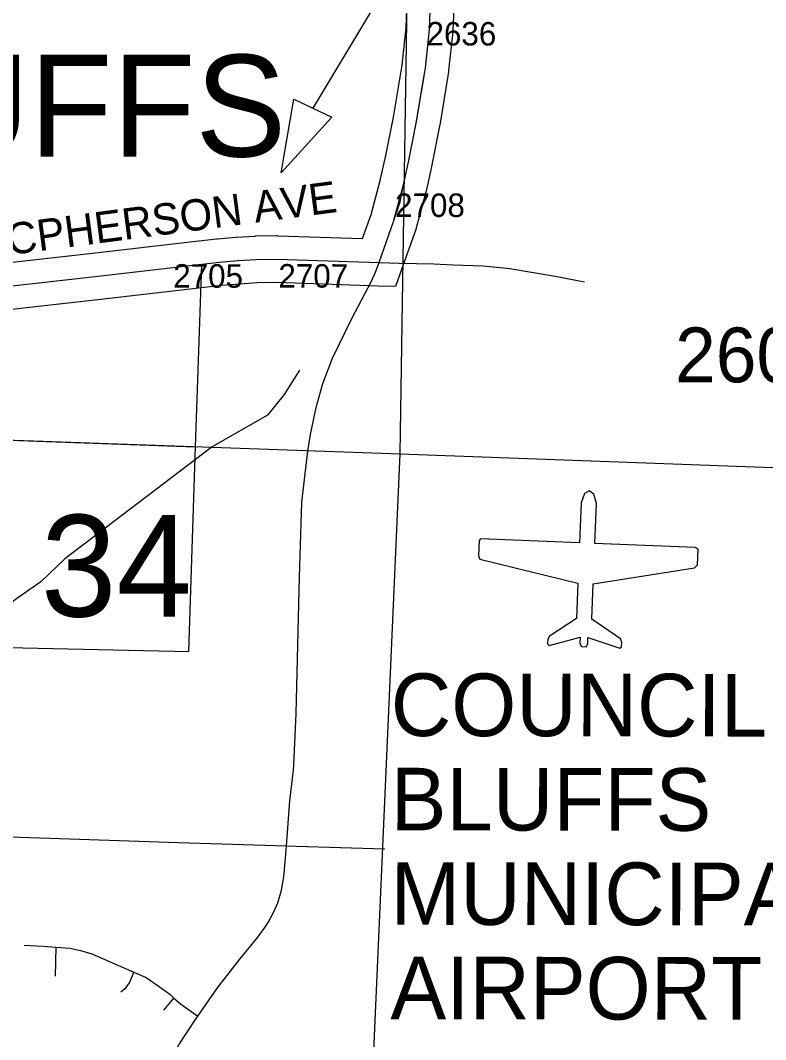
# Model space of a CAD drawing. Extents: x -132.8 to -73.3, y -60 to -26.
# Drawn here: x -118.384 to -117.43, y -50.173 to -48.87 of the extents above; entities that cross this region are included whole.
import ezdxf

# ---------------------------------------------------------------- set-up
doc = ezdxf.new("R2010")
doc.units = 0
for name, color, linetype in [('tdCoAirport', 7, 'Continuous'), ('tdCoAirportTxt', 7, 'Continuous'), ('tdCoCityStreetMajor', 7, 'Continuous'), ('tdCoCityStreetMinor', 7, 'Continuous'), ('tdCoCorpBndry', 7, 'Continuous'), ('tdCoCorpTxt', 7, 'Continuous'), ('tdCoDirctArrow', 7, 'Continuous'), ('tdCoHydroRiver', 7, 'Continuous'), ('tdCoSecRdNmbr', 7, 'Continuous'), ('tdCoSecRdTxt', 7, 'Continuous'), ('tdCoSecRteBand', 7, 'Continuous'), ('tdCoSecRteCL', 7, 'Continuous'), ('tdCoSectLine', 7, 'Continuous'), ('tdCoSectLinePart', 7, 'Continuous'), ('tdCoSectNmbr', 7, 'Continuous'), ('tdCoSurfAsphalt', 7, 'Continuous'), ('tdCoSurfConc', 7, 'Continuous')]:
    doc.layers.add(name, color=color, linetype=linetype)

msp = doc.modelspace()

# ---------------------------------------------------------------- linework, layer by layer
at = {"layer": 'tdCoAirport'}
msp.add_lwpolyline([(-117.6559, -49.4714), (-117.662, -49.4751), (-117.6664, -49.4868), (-117.6685, -49.5381), (-117.7949, -49.533), (-117.7969, -49.5349), (-117.7977, -49.5546), (-117.7959, -49.5587), (-117.6706, -49.5895), (-117.6724, -49.6349), (-117.7069, -49.6572), (-117.7091, -49.6611), (-117.7093, -49.667), (-117.7074, -49.6691), (-117.6674, -49.6588), (-117.6678, -49.6667), (-117.6659, -49.6707), (-117.66, -49.671), (-117.6579, -49.6671), (-117.6576, -49.6592), (-117.6166, -49.6728), (-117.6145, -49.6709), (-117.6143, -49.6649), (-117.6161, -49.6609), (-117.6527, -49.6357), (-117.6508, -49.5903), (-117.5214, -49.5698), (-117.5173, -49.566), (-117.5165, -49.5463), (-117.5204, -49.5441), (-117.6487, -49.5389), (-117.6467, -49.4876), (-117.6484, -49.4816), (-117.6501, -49.4756)], close=True, dxfattribs=at)
at = {"layer": 'tdCoCityStreetMajor'}
msp.add_lwpolyline([(-118.4228, -49.9132), (-118.41, -49.9134), (-118.1814, -49.9211), (-118.0432, -49.9253), (-118.039, -49.8676), (-118.0342, -49.8288), (-118.0337, -49.8224), (-118.0309, -49.7562), (-118.0267, -49.5816), (-118.0234, -49.4859), (-118.0159, -49.421), (-118.0124, -49.3997), (-118.0053, -49.3652), (-117.9967, -49.3343), (-117.9845, -49.302), (-117.9593, -49.2502), (-117.9349, -49.2042), (-117.9292, -49.192), (-117.9248, -49.1798)], dxfattribs=at)
at = {"layer": 'tdCoCityStreetMinor'}
for p, q in [((-118.3385, -50.0918), (-118.3378, -50.0547)), ((-118.2003, -50.1354), (-118.1872, -50.12))]:
    msp.add_line(p, q, dxfattribs=at)
for points in [[(-117.9248, -49.1798), (-117.899, -49.1804), (-117.8546, -49.1815), (-117.8302, -49.1825), (-117.7915, -49.184), (-117.7577, -49.1872), (-117.6995, -49.1973), (-117.6618, -49.2046)], [(-118.1567, -50.143), (-118.1315, -50.1067), (-118.1027, -50.0702), (-118.08, -50.0421), (-118.0719, -50.031), (-118.0667, -50.0231), (-118.0598, -50.0105), (-118.0541, -49.9982), (-118.0497, -49.9819), (-118.0467, -49.9649), (-118.0447, -49.9457), (-118.0432, -49.9253), (-118.0308, -49.9257), (-117.9175, -49.9292)], [(-118.3786, -50.0524), (-118.3543, -50.0536), (-118.3378, -50.0547)], [(-118.3378, -50.0547), (-118.3202, -50.0561), (-118.3068, -50.0589), (-118.2922, -50.0635), (-118.2384, -50.0869)], [(-118.255, -50.112), (-118.2481, -50.1066), (-118.2439, -50.1004), (-118.2384, -50.0869)], [(-118.2384, -50.0869), (-118.2228, -50.0935), (-118.2072, -50.1042), (-118.1926, -50.1151), (-118.1872, -50.12)], [(-118.1872, -50.12), (-118.1789, -50.1273), (-118.1567, -50.143)], [(-118.2083, -50.229), (-118.2006, -50.2142), (-118.1799, -50.1785), (-118.1589, -50.1461), (-118.1567, -50.143)]]:
    msp.add_lwpolyline(points, dxfattribs=at)
at = {"layer": 'tdCoCorpBndry'}
msp.add_lwpolyline([(-118.4192, -49.6715), (-118.168, -49.6767), (-118.1596, -49.4151), (-118.1516, -49.1819), (-118.1293, -49.1793), (-118.1052, -49.1773), (-118.082, -49.1758), (-118.0553, -49.1753), (-117.9248, -49.1798), (-117.9062, -49.1274), (-117.898, -49.102), (-117.894, -49.0821), (-117.8868, -49.0491), (-117.8768, -48.9995), (-117.8684, -48.9481), (-117.8656, -48.9313), (-117.8604, -48.8817), (-117.8589, -48.845)], dxfattribs=at)
at = {"layer": 'tdCoDirctArrow'}
msp.add_lwpolyline([(-117.1819, -48.8561), (-117.933, -48.8556), (-118.0095, -48.9824)], dxfattribs=at)
msp.add_lwpolyline([(-117.9851, -48.9939), (-118.0499, -49.0652), (-118.0338, -48.9709)], close=True, dxfattribs=at)
at = {"layer": 'tdCoHydroRiver'}
msp.add_lwpolyline([(-118.0266, -49.3174), (-118.0464, -49.3484), (-118.0676, -49.3747), (-118.1382, -49.4153), (-118.3267, -49.5586), (-118.3575, -49.5877), (-118.3897, -49.6105), (-118.4219, -49.6365), (-118.4749, -49.6697), (-118.5026, -49.7021), (-118.5162, -49.738), (-118.5248, -49.763), (-118.5361, -49.7738), (-118.5511, -49.8018), (-118.5819, -49.8341), (-118.6048, -49.865), (-118.6578, -49.9551), (-118.7293, -50.092), (-118.7676, -50.1571)], dxfattribs=at)
at = {"layer": 'tdCoSecRteBand'}
for points in [[(-118.4091, -49.1808), (-118.2913, -49.1677), (-118.1552, -49.1521), (-118.1552, -49.1521), (-118.1552, -49.1521), (-118.1551, -49.1521), (-118.1328, -49.1495), (-118.1323, -49.1494), (-118.1318, -49.1494), (-118.1076, -49.1474), (-118.1073, -49.1474), (-118.1071, -49.1474), (-118.0839, -49.1459), (-118.0832, -49.1459), (-118.0825, -49.1458), (-118.0559, -49.1453), (-118.0551, -49.1453), (-118.0543, -49.1454), (-117.9458, -49.1491), (-117.9349, -49.1184), (-117.9232, -49.075), (-117.9162, -49.0429), (-117.9063, -48.9941), (-117.8953, -48.9273), (-117.8903, -48.8795), (-117.8889, -48.844)], [(-117.8289, -48.8462), (-117.8304, -48.8829), (-117.8305, -48.8839), (-117.8306, -48.8848), (-117.8358, -48.9344), (-117.8359, -48.9353), (-117.836, -48.9361), (-117.8472, -49.0043), (-117.8473, -49.0049), (-117.8474, -49.0054), (-117.8574, -49.055), (-117.8575, -49.0552), (-117.8575, -49.0554), (-117.8647, -49.0885), (-117.8649, -49.0892), (-117.865, -49.0899), (-117.8772, -49.1352), (-117.8775, -49.1363), (-117.8779, -49.1374), (-117.8966, -49.1899), (-117.9039, -49.2105), (-117.9259, -49.2098), (-118.0556, -49.2054), (-118.0807, -49.2058), (-118.103, -49.2072), (-118.1264, -49.2091), (-118.1482, -49.2117), (-118.1482, -49.2117), (-118.1482, -49.2117), (-118.1483, -49.2117), (-118.2845, -49.2273), (-118.2845, -49.2273), (-118.2846, -49.2274), (-118.4024, -49.2404)]]:
    msp.add_lwpolyline(points, dxfattribs=at)
at = {"layer": 'tdCoSecRteCL'}
msp.add_lwpolyline([(-118.4058, -49.2106), (-118.2879, -49.1975), (-118.1517, -49.1819), (-118.1516, -49.1819), (-118.1293, -49.1793), (-118.1052, -49.1773), (-118.082, -49.1758), (-118.0553, -49.1753), (-117.9248, -49.1798), (-117.9062, -49.1274), (-117.894, -49.0821), (-117.8868, -49.0491), (-117.8768, -48.9995), (-117.8656, -48.9313), (-117.8604, -48.8817), (-117.8589, -48.845)], dxfattribs=at)
at = {"layer": 'tdCoSectLine'}
for points in [[(-117.8978, -49.4244), (-117.8824, -48.4302)], [(-118.909, -49.3886), (-117.8978, -49.4244)], [(-117.9423, -50.429), (-117.8978, -49.4244)], [(-117.8978, -49.4244), (-116.9091, -49.4603)]]:
    msp.add_lwpolyline(points, dxfattribs=at)
at = {"layer": 'tdCoSectLinePart'}
msp.add_lwpolyline([(-118.909, -49.3886), (-118.1599, -49.4151)], dxfattribs=at)
at = {"layer": 'tdCoSurfAsphalt'}
msp.add_lwpolyline([(-118.4058, -49.2106), (-118.2879, -49.1975), (-118.1517, -49.1819), (-118.1516, -49.1819), (-118.1293, -49.1793), (-118.1052, -49.1773), (-118.082, -49.1758), (-118.0553, -49.1753), (-117.9248, -49.1798)], dxfattribs=at)
at = {"layer": 'tdCoSurfConc'}
msp.add_lwpolyline([(-117.9248, -49.1798), (-117.9062, -49.1274), (-117.894, -49.0821), (-117.8868, -49.0491), (-117.8768, -48.9995), (-117.8656, -48.9313), (-117.8604, -48.8817), (-117.8589, -48.845)], dxfattribs=at)

# ---------------------------------------------------------------- texts
at = {"layer": 'tdCoAirportTxt'}
for s, p in [('COUNCIL', (-117.9098, -49.7849)), ('BLUFFS', (-117.91, -49.9055)), ('MUNICIPAL', (-117.9101, -50.0262)), ('AIRPORT', (-117.9103, -50.1469))]:
    msp.add_text(s, height=0.08, rotation=359.9124, dxfattribs=at).set_placement(p)
at = {"layer": 'tdCoCorpTxt'}
msp.add_text('BLUFFS', height=0.13, dxfattribs=at).set_placement((-118.7102, -49.0442))
at = {"layer": 'tdCoSecRdNmbr'}
for s, height, rotation, p in [('2636', 0.03, 359.9115, (-117.8641, -48.9022)), ('2708', 0.03, 359.9115, (-117.9043, -49.1214)), ('2705', 0.03, 359.9115, (-118.1881, -49.2118)), ('2707', 0.03, 359.9115, (-118.0536, -49.2117)), ('2609', 0.07, 359.9121, (-117.5462, -49.3327))]:
    msp.add_text(s, height=height, rotation=rotation, dxfattribs=at).set_placement(p)
at = {"layer": 'tdCoSecRdTxt'}
msp.add_text('MCPHERSON AVE', height=0.04, rotation=7.4762, dxfattribs=at).set_placement((-118.4425, -49.1761))
at = {"layer": 'tdCoSectNmbr'}
msp.add_text('34', height=0.13, rotation=359.9115, dxfattribs=at).set_placement((-118.3575, -49.6322))

doc.saveas('drawing.dxf')
